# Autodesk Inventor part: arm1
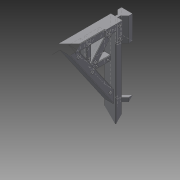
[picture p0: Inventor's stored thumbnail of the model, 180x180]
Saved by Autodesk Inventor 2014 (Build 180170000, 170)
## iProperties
Created: 2013-07
Part Number: arm1
Material: Generic
Document SubType Name: Modeling
Designer: Brent J. Rosenburgh
Density: 1 g/cm^3
Appearance: Default
Author: Brent J. Rosenburgh
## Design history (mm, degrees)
sketch "Sketch1"
  geometry: L1 (-7, 5)-(7, 5); L2 (7, 5)-(7, 0); L3 (7, 0)-(2, -5); L4 (-7, 5)-(-7, 0); L5 (-7, 0)-(-2, -5); L6 (-2, -5)-(-1.627, -5.373); L7 (-1.627, -5.373)-(-1.627, -8.541); L8 (2, -5)-(1.627, -5.373); L9 (1.627, -5.373)-(1.627, -8.541); L10 (1.627, -8.541)-(7, -8.541); L11 (-1.627, -8.541)-(-7, -8.541); L12 (-7, -8.541)-(-7, -16.541); L13 (-7, -16.541)-(7, -16.541); L14 (7, -16.541)-(7, -8.541); 1 further point
  constraints: 28 end point, 5 parallel, 5 perpendicular, 2 collinear, 1 horizontal
  dimensions: "d0" = 8 distance of L11.end L12.end
extrude "Extrusion1" new body sketch "Sketch1" distance "d1" = 119; taper "d2" = 0 deg
sketch "Sketch2"
  geometry: L1 (0, 8)-(-119, 8) reference; L2 (-30, 8)-(-89, 8); L3 (-89, 8)-(-89, 24); L4 (-89, 24)-(-30, 24); L5 (-30, 24)-(-30, 8); 1 further point
  constraints: 8 end point, 2 parallel, 1 horizontal, 1 perpendicular, 1 point on line
extrude "Extrusion2" cut sketch "Sketch2" distance "d3" = 19; taper "d4" = 0 deg
sketch "Sketch3"
  geometry: L1 (0, 0)-(119, 0) reference; L2 (0, 8)-(119, 8) reference; L3 (119, 0)-(119, -80); L4 (119, -80)-(111, -80); L5 (111, -80)-(111, 0); 1 further point
  constraints: 6 end point, 2 perpendicular, 1 parallel, 1 point on line
extrude "Extrusion3" join sketch "Sketch3" distance "d5" = 14; taper "d6" = 0 deg
sketch "Sketch4"
  geometry: L1 (0, 0)-(111, 0) reference; L2 (111, 0)-(111, -80) reference; L3 (111, -56)-(30, 0); L4 (46, 0)-(111, -44.938); 1 further point
  constraints: 4 end point, 4 point on line, 1 parallel
extrude "Extrusion4" join sketch "Sketch4" distance "d7" = 12; taper "d8" = 0 deg
sketch "Sketch5"
  geometry: L1 (46, 0)-(111, 0) reference; L2 (111, 0)-(111, -44.938) reference; L3 (111, -44.938)-(46, 0) reference; L4 (105, 0)-(78.5, -22.469); L5 (111, -6)-(85.703, -27.449); 1 further point
  constraints: 4 end point, 3 point on line, 1 midpoint, 1 parallel
extrude "Extrusion5" join sketch "Sketch5" distance "d9" = 10; taper "d10" = 0 deg
sketch "Sketch6"
  geometry: L1 (81.627, 3)-(75.061, 3); L2 (75.061, 3)-(75.061, -25.469); L3 (75.061, -25.469)-(81.627, -25.469); L4 (81.627, -25.469)-(81.627, 3); L5 (113, -24.592)-(81.627, -24.592); L6 (81.627, -24.592)-(81.627, -30.232); L7 (81.627, -30.232)-(113, -30.232); L8 (113, -30.232)-(113, -24.592); 1 further point
  constraints: 16 end point, 4 parallel, 2 horizontal, 2 perpendicular
extrude "Extrusion6" join sketch "Sketch6" distance "d11" = 8; taper "d12" = 0 deg
sketch "Sketch7"
  geometry: L1 (0, 8)-(-119, 8) reference; L2 (-119, 8)-(-119, -80) reference; L3 (-111, -80)-(-111, 0) reference; L4 (0, 0)-(-111, 0) reference; L5 (-97, 0)-(-97, 8); L6 (-111, -14)-(-119, -14); 1 further point
  constraints: 4 end point, 4 point on line, 2 perpendicular
extrude "Extrusion7" join sketch "Sketch7" distance "d13" = 1; taper "d14" = 0 deg
sketch "Sketch8"
  geometry: L1 (-103.938, -47.474)-(-105.67, -46.474); L2 (-105.67, -46.474)-(-105.67, -44.474); L3 (-105.67, -44.474)-(-103.938, -43.474); L4 (-103.938, -43.474)-(-102.206, -44.474); L5 (-102.206, -44.474)-(-102.206, -46.474); L6 (-102.206, -46.474)-(-103.938, -47.474); L7 (-45, -7)-(-46.732, -6); L8 (-46.732, -6)-(-46.732, -4); L9 (-46.732, -4)-(-45, -3); L10 (-45, -3)-(-43.268, -4); L11 (-43.268, -4)-(-43.268, -6); L12 (-43.268, -6)-(-45, -7); L13 (-78.5, -25.888)-(-76.768, -26.888); L14 (-80.232, -26.888)-(-78.5, -25.888); L15 (-76.768, -28.888)-(-78.5, -29.888); L16 (-80.232, -28.888)-(-80.232, -26.888); L17 (-78.5, -29.888)-(-80.232, -28.888); L18 (-76.768, -26.888)-(-76.768, -28.888); 4 further points
  constraints: 36 end point, 39 other
extrude "Extrusion8" join sketch "Sketch8" distance "d15" = 1; taper "d16" = 0 deg
sketch "Sketch9"
  geometry: L1 (-101, 2)-(-102.732, 3); L2 (-102.732, 3)-(-102.732, 5); L3 (-102.732, 5)-(-101, 6); L4 (-101, 6)-(-99.268, 5); L5 (-99.268, 5)-(-99.268, 3); L6 (-99.268, 3)-(-101, 2); L7 (-115, -12)-(-116.732, -11); L8 (-116.732, -11)-(-116.732, -9); L9 (-116.732, -9)-(-115, -8); L10 (-115, -8)-(-113.268, -9); L11 (-113.268, -9)-(-113.268, -11); L12 (-113.268, -11)-(-115, -12); L13 (-115, 2)-(-116.732, 3); L14 (-116.732, 3)-(-116.732, 5); L15 (-116.732, 5)-(-115, 6); L16 (-115, 6)-(-113.268, 5); L17 (-113.268, 5)-(-113.268, 3); L18 (-113.268, 3)-(-115, 2); 4 further points
  constraints: 36 end point, 39 other
extrude "Extrusion9" join sketch "Sketch9" distance "d17" = 1; taper "d18" = 0 deg
sketch "Sketch10"
  geometry: L1 (-106, -7)-(-107.732, -6); L2 (-107.732, -6)-(-107.732, -4); L3 (-107.732, -4)-(-106, -3); L4 (-106, -3)-(-104.268, -4); L5 (-104.268, -4)-(-104.268, -6); L6 (-104.268, -6)-(-106, -7); L7 (-85.703, -24)-(-87.435, -23); L8 (-87.435, -23)-(-87.435, -21); L9 (-87.435, -21)-(-85.703, -20); L10 (-85.703, -20)-(-83.971, -21); L11 (-83.971, -21)-(-83.971, -23); L12 (-83.971, -23)-(-85.703, -24); 3 further points
  constraints: 24 end point, 26 other
extrude "Extrusion10" join sketch "Sketch10" distance "d19" = 1; taper "d20" = 0 deg
sketch "Sketch11"
  geometry: L1 (-79.811, -18)-(-79.155, -16.865); L2 (-79.155, -16.865)-(-77.845, -16.865); L3 (-77.845, -16.865)-(-77.189, -18); L4 (-77.189, -18)-(-77.845, -19.135); L5 (-77.845, -19.135)-(-79.155, -19.135); L6 (-79.155, -19.135)-(-79.811, -18); L7 (-79.811, -4)-(-79.155, -2.865); L8 (-79.155, -2.865)-(-77.845, -2.865); L9 (-77.845, -2.865)-(-77.189, -4); L10 (-77.189, -4)-(-77.845, -5.135); L11 (-77.845, -5.135)-(-79.155, -5.135); L12 (-79.155, -5.135)-(-79.811, -4); 3 further points
  constraints: 24 end point, 26 other
extrude "Extrusion11" join sketch "Sketch11" distance "d21" = 1; taper "d22" = 0 deg
sketch "Sketch12"
  geometry: L1 (-107, -28.841)-(-108.237, -28.126); L2 (-108.237, -28.126)-(-108.237, -26.698); L3 (-108.237, -26.698)-(-107, -25.983); L4 (-107, -25.983)-(-105.763, -26.698); L5 (-105.763, -26.698)-(-105.763, -28.126); L6 (-105.763, -28.126)-(-107, -28.841); L7 (-92, -28.841)-(-93.237, -28.126); L8 (-93.237, -28.126)-(-93.237, -26.698); L9 (-93.237, -26.698)-(-92, -25.983); L10 (-92, -25.983)-(-90.763, -26.698); L11 (-90.763, -26.698)-(-90.763, -28.126); L12 (-90.763, -28.126)-(-92, -28.841); 3 further points
  constraints: 24 end point, 26 other
extrude "Extrusion12" join sketch "Sketch12" distance "d23" = 1; taper "d24" = 0 deg
sketch "Sketch13"
  geometry: L1 (14, 0)-(-8, 0); L2 (-8, 0)-(-8, 22); L3 (-8, 22)-(14, 22); L4 (14, 22)-(14, 0); 1 further point
  constraints: 8 end point, 2 parallel, 1 horizontal, 1 perpendicular
extrude "Extrusion13" join sketch "Sketch13" distance "d25" = 8; taper "d26" = 0 deg
chamfer "Chamfer1" distance "d27" = 8; stored, may be unused: second distance "d28" = 2, angle "d29" = 45 deg
chamfer "Chamfer2" distance "d30" = 5; stored, may be unused: second distance "d31" = 2, angle "d32" = 45 deg
sketch "Sketch14"
  geometry: L1 (8.5, -9.364)-(8.449, -15.556); L2 (8.449, -15.556)-(4.034, -19.898); L3 (4.034, -19.898)-(-2.158, -19.847); L4 (-2.158, -19.847)-(-6.5, -15.432); L5 (-6.5, -15.432)-(-6.449, -9.24); L6 (-6.449, -9.24)-(-2.034, -4.898); L7 (-2.034, -4.898)-(4.158, -4.949); L8 (4.158, -4.949)-(8.5, -9.364); 2 further points
  constraints: 16 end point, 17 other
extrude "Extrusion14" cut sketch "Sketch14" distance "d33" = 4; taper "d34" = 0 deg
sketch "Sketch15"
  geometry: C1 r 3 at (0.938, -12.335); 1 further point
  constraints: 1 centre point
  dimensions: "d35" = 6 diameter of C1
extrude "Extrusion15" cut sketch "Sketch15" distance "d36" = 4; taper "d37" = 0 deg
chamfer "Chamfer3" distance "d38" = 3; stored, may be unused: second distance "d39" = 2, angle "d40" = 45 deg
chamfer "Chamfer4" distance "d41" = 1; stored, may be unused: second distance "d42" = 2, angle "d43" = 45 deg
chamfer "Chamfer5" distance "d44" = 0.6; stored, may be unused: second distance "d45" = 2, angle "d46" = 45 deg
chamfer "Chamfer6" distance "d47" = 0.6; stored, may be unused: second distance "d48" = 2, angle "d49" = 45 deg
chamfer "Chamfer7" distance "d50" = 1.85; stored, may be unused: second distance "d51" = 2, angle "d52" = 45 deg
body "Solid1"
